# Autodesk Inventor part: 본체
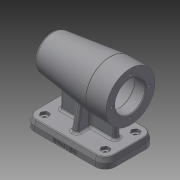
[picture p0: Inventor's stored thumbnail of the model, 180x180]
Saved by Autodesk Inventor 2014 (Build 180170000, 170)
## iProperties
Created: 2017-01
Part Number: 본체
Material: 일반
Document SubType Name: Modeling
Designer: USER
Density: 1 g/cm^3
Appearance: 기본값
Author: USER
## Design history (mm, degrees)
sketch "스케치1"
  geometry: L1 (0, 0)-(112, 0); L2 (112, 0)-(112, -70); L3 (112, -70)-(0, -70); L4 (0, -70)-(0, 0)
  constraints: 8 end point, 2 parallel, 1 horizontal, 1 perpendicular
  dimensions: "d0" = 112 distance of L1.start L1.end; "d1" = 70 distance of L3.end L1.start
extrude "돌출1" new body sketch "스케치1" distance "d2" = 14; taper "d3" = 0 deg
node "작업 평면1"
sketch "스케치3"
  geometry: L1 (0, 74)-(112, 74); L2 (0, 0)-(112, 0) reference; L3 (112, 74)-(112, 108); L4 (112, 108)-(84, 108); L5 (84, 108)-(3.73, 98.144); A1 r 80 centre (80, 74) between (3.73, 98.144) and (0, 74); 1 further point
  constraints: 8 end point, 2 perpendicular, 2 point on circle, 1 centre point, 1 horizontal, 1 point on line, 1 vertical alignment
  dimensions: "d16" = 74 distance between parallel lines of L2 L1; "d17" = 112 distance of L1.start L1.end; "d19" = 7 deg angle of L4 L5; "d20" = 28 distance of L3.end L4.end; "d21" = 68 diameter of L4 L1; "d26" = 80 distance of A1.centre L1.start
revolve "회전1" sketch "스케치3" stored, may be unused: angle "d27" = 90 deg
fillet "모깎기1" dims "d28" = 3
sketch "스케치4"
  geometry: C1 r 34 at (0, 0) reference; C2 r 21 at (0, 0); 1 further point
  constraints: 1 centre point, 1 coincident
  dimensions: "d29" = 42 diameter of C2
extrude "돌출2" cut sketch "스케치4" distance "d30" = 15; taper "d31" = 0 deg
sketch "스케치5"
  geometry: C1 r 21 at (0, 0) reference; C2 r 24 at (0, 0); 1 further point
  constraints: 1 centre point, 1 coincident
  dimensions: "d32" = 48 diameter of C2
extrude "돌출3" cut sketch "스케치5" distance "d33" = 54; taper "d34" = 0 deg
sketch "스케치6"
  geometry: C1 r 24 at (0, 0) reference; C2 r 21 at (0, 0); 1 further point
  constraints: 1 centre point, 1 coincident
  dimensions: "d35" = 42 diameter of C2
extrude "돌출4" cut sketch "스케치6" distance "d36" = 12; taper "d37" = 0 deg
sketch "스케치7"
  geometry: C1 r 21 at (0, 0) reference; C2 r 17.5 at (0, 0); 1 further point
  constraints: 1 centre point, 1 coincident
  dimensions: "d38" = 35 diameter of C2
extrude "돌출5" cut sketch "스케치7" distance "d39" = 18; taper "d40" = 0 deg
sketch "스케치8"
  geometry: C1 r 17.5 at (0, 0) reference; C2 r 16 at (0, 0); 1 further point
  constraints: 1 centre point, 1 coincident
  dimensions: "d41" = 32 diameter of C2
extrude "돌출6" cut sketch "스케치8" distance "d42" = 4; taper "d43" = 0 deg
sketch "스케치9"
  geometry: C1 r 16 at (0, 0) reference; C2 r 10.5 at (0, 0); 1 further point
  constraints: 1 centre point, 1 coincident
  dimensions: "d44" = 21 diameter of C2
extrude "돌출7" cut sketch "스케치9" distance "d45" = 3; taper "d46" = 0 deg
fillet "모깎기2" dims "d47" = 3
fillet "모깎기3" dims "d48" = 0.3
fillet "모깎기4" dims "d49" = 3
node "작업 평면2"
fillet "모깎기8" dims "d130" = 14
chamfer "모따기5" distance "d68" = 1; stored, may be unused: second distance "d69" = 2, angle "d70" = 45 deg
fillet "모깎기6" dims "d71" = 3
fillet "모깎기7" dims "d72" = 3
sketch "스케치14"
  geometry: C1 r 34 at (0, 0) reference; C2 r 22 at (0, 0) reference; A1 r 26 centre (0, 0) between (-26, 0) and (0, -26); 3 further points
  constraints: 4 point on circle, 2 horizontal alignment, 2 vertical alignment, 1 centre point, 1 coincident
  dimensions: "d73" = 52 diameter of A1
hole "구멍1" sketch "스케치14" at (-26, 0), (0, -26), (26, 0), (0, 26) diameter "d74" = 3.242; stored, may be unused: countersink angle "d78" = 90 deg, drill point angle "d80" = 118 deg; dims "d75" = 8, "d76" = 4, "d77" = 2, "d79" = 11
chamfer "모따기6" distance "d131" = 7; stored, may be unused: second distance "d132" = 2, angle "d133" = 15 deg
sketch "스케치22"
  geometry: L1 (14, -1.876)-(98, -1.876) reference; L2 (1.876, -56)-(1.876, -14) reference; L3 (18, -31)-(94, -31); L4 (94, -31)-(94, -39); L5 (94, -39)-(18, -39); L6 (18, -39)-(18, -31); 5 further points
  constraints: 8 end point, 4 midpoint, 2 parallel, 1 horizontal, 1 horizontal alignment, 1 perpendicular, 1 vertical alignment
  dimensions: "d134" = 76 distance of L3.start L3.end; "d135" = 8 distance of L5.end L3.start
extrude "돌출16" join sketch "스케치22" stored distance "d136" = 4; taper "d137" = 0 deg
node "작업 평면8"
sketch "스케치23"
  geometry: L1 (0, -17)-(0, 25) reference; L2 (0, -29.124)-(0, -17) reference; L3 (0, 25)-(0, 37.124) reference; L4 (0, -19)-(-38.397, -12.23); L5 (0, 27)-(-38.15, 20.273); L6 (14, -31)-(7, -31) reference; L7 (7, 39)-(14, 39) reference
  constraints: 4 end point, 2 point on line
  dimensions: "d138" = 12 distance from line of L6 L4.start; "d139" = 100 deg angle of L2 L4; "d140" = 100 deg angle of L3 L5; "d141" = 12 distance from line of L7 L5.start
feature "리브3" dims "d142" = 1, "d143" = 8, "d144" = 0, "d145" = 0, "d146" = 1, "d147" = 1
feature "리브4" dims "d148" = 1, "d149" = 8, "d150" = 0, "d151" = 0, "d152" = 1, "d153" = 1
fillet "모깎기9" dims "d154" = 1
fillet "모깎기10" dims "d155" = 3
fillet "모깎기11" dims "d156" = 3
sketch "스케치25"
  geometry: L1 (16.887, -9)-(19.774, -14); L2 (19.774, -14)-(16.887, -19); L3 (16.887, -19)-(11.113, -19); L4 (11.113, -19)-(8.226, -14); L5 (8.226, -14)-(11.113, -9); L6 (11.113, -9)-(16.887, -9); L7 (92.226, -14)-(95.113, -9); L8 (95.113, -9)-(100.887, -9); L9 (100.887, -9)-(103.774, -14); L10 (103.774, -14)-(100.887, -19); L11 (100.887, -19)-(95.113, -19); L12 (95.113, -19)-(92.226, -14); L13 (100.887, -51)-(103.774, -56); L14 (103.774, -56)-(100.887, -61); L15 (100.887, -61)-(95.113, -61); L16 (95.113, -61)-(92.226, -56); L17 (92.226, -56)-(95.113, -51); L18 (95.113, -51)-(100.887, -51); L19 (19.774, -56)-(16.887, -61); L20 (16.887, -61)-(11.113, -61); L21 (11.113, -61)-(8.226, -56); L22 (8.226, -56)-(11.113, -51); L23 (11.113, -51)-(16.887, -51); L24 (16.887, -51)-(19.774, -56); C1 r 5 at (14, -14); C2 r 5 at (98, -14); C3 r 5 at (14, -56); C4 r 5 at (98, -56); A1 r 11.357 centre (14, -56) between (2.643, -56) and (14, -67.357) reference; A2 r 11.357 centre (98, -56) between (98, -67.357) and (109.357, -56) reference; A3 r 11.357 centre (98, -14) between (109.357, -14) and (98, -2.643) reference; A4 r 11.357 centre (14, -14) between (14, -2.643) and (2.643, -14) reference; 9 further points
  constraints: 48 end point, 8 coincident, 4 centre point, 4 horizontal alignment, 4 midpoint, 4 tangent, 4 vertical alignment, 52 other
  dimensions: "d157" = 10 diameter of C1; "d158" = 10 diameter of C2; "d159" = 10 diameter of C3; "d160" = 10 diameter of C4
extrude "돌출17" cut sketch "스케치25" distance "d161" = 4; taper "d162" = 0 deg
sketch "스케치26"
  geometry: C1 r 2.5 at (-98, -14); C2 r 2.5 at (-14, -14); C3 r 2.5 at (-14, -56); C4 r 2.5 at (-98, -56); A1 r 14 centre (-14, -56) between (-14, -70) and (0, -56) reference; A2 r 14 centre (-14, -14) between (0, -14) and (-14, 0) reference; A3 r 14 centre (-98, -14) between (-98, 0) and (-112, -14) reference; A4 r 14 centre (-98, -56) between (-112, -56) and (-98, -70) reference; 1 further point
  constraints: 4 centre point, 4 coincident
  dimensions: "d163" = 5 diameter of C1; "d164" = 5 diameter of C2; "d165" = 5 diameter of C3; "d166" = 5 diameter of C4
extrude "돌출18" cut sketch "스케치26" stored distance "d167" = 4; taper "d168" = 0 deg
sketch "스케치28"
  geometry: L1 (84, 0)-(0, 0) reference; L2 (0, 13.259)-(84, 13.259) reference; 3 further points
  constraints: 1 midpoint, 1 vertical alignment, 1 other
  dimensions: "d169" = 4 distance from line of L1 point (42, 4)
extrude "돌출19" join sketch "스케치28" distance "d170" = 0.5; taper "d171" = 0 deg
node "솔리드1"
